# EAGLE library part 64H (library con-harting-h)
CONNECTOR
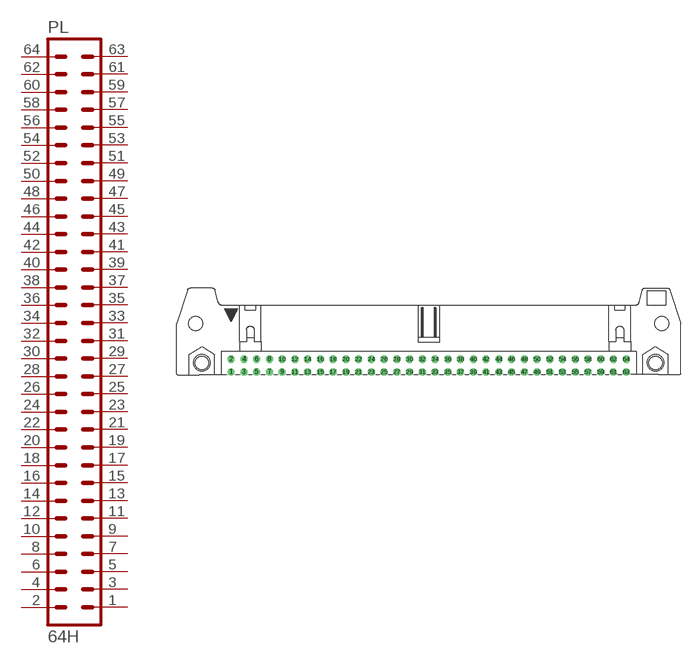
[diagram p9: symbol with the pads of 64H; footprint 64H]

Designator prefix PL

## 64H (OC_FARNELL: unknown; OC_NEWARK: unknown)  [64H]
1  1  pas
2  2  pas
3  3  pas
4  4  pas
5  5  pas
6  6  pas
7  7  pas
8  8  pas
9  9  pas
10  10  pas
11  11  pas
12  12  pas
13  13  pas
14  14  pas
15  15  pas
16  16  pas
17  17  pas
18  18  pas
19  19  pas
20  20  pas
21  21  pas
22  22  pas
23  23  pas
24  24  pas
25  25  pas
26  26  pas
27  27  pas
28  28  pas
29  29  pas
30  30  pas
31  31  pas
32  32  pas
33  33  pas
34  34  pas
35  35  pas
36  36  pas
37  37  pas
38  38  pas
39  39  pas
40  40  pas
41  41  pas
42  42  pas
43  43  pas
44  44  pas
45  45  pas
46  46  pas
47  47  pas
48  48  pas
49  49  pas
50  50  pas
51  51  pas
52  52  pas
53  53  pas
54  54  pas
55  55  pas
56  56  pas
57  57  pas
58  58  pas
59  59  pas
60  60  pas
61  61  pas
62  62  pas
63  63  pas
64  64  pas

## Footprint 64H (pad centres in mm)
CONNECTOR
drill 0.914 round: 1 -39.37,-1.27
drill 0.914 octagon: 2 -39.37,1.27; 3 -36.83,-1.27; 4 -36.83,1.27; 5 -34.29,-1.27; 6 -34.29,1.27; 7 -31.75,-1.27; 8 -31.75,1.27; 9 -29.21,-1.27; 10 -29.21,1.27; 11 -26.67,-1.27; 12 -26.67,1.27; 13 -24.13,-1.27; 14 -24.13,1.27; 15 -21.59,-1.27; 16 -21.59,1.27; 17 -19.05,-1.27; 18 -19.05,1.27; 19 -16.51,-1.27; 20 -16.51,1.27; 21 -13.97,-1.27; 22 -13.97,1.27; 23 -11.43,-1.27; 24 -11.43,1.27; 25 -8.89,-1.27; 26 -8.89,1.27; 27 -6.35,-1.27; 28 -6.35,1.27; 29 -3.81,-1.27; 30 -3.81,1.27; 31 -1.27,-1.27; 32 -1.27,1.27; 33 1.27,-1.27; 34 1.27,1.27; 35 3.81,-1.27; 36 3.81,1.27; 37 6.35,-1.27; 38 6.35,1.27; 39 8.89,-1.27; 40 8.89,1.27; 41 11.43,-1.27; 42 11.43,1.27; 43 13.97,-1.27; 44 13.97,1.27; 45 16.51,-1.27; 46 16.51,1.27; 47 19.05,-1.27; 48 19.05,1.27; 49 21.59,-1.27; 50 21.59,1.27; 51 24.13,-1.27; 52 24.13,1.27; 53 26.67,-1.27; 54 26.67,1.27; 55 29.21,-1.27; 56 29.21,1.27; 57 31.75,-1.27; 58 31.75,1.27; 59 34.29,-1.27; 60 34.29,1.27; 61 36.83,-1.27; 62 36.83,1.27; 63 39.37,-1.27; 64 39.37,1.27
hole 3.302 at -45.212,0.533
hole 3.302 at 45.212,0.533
